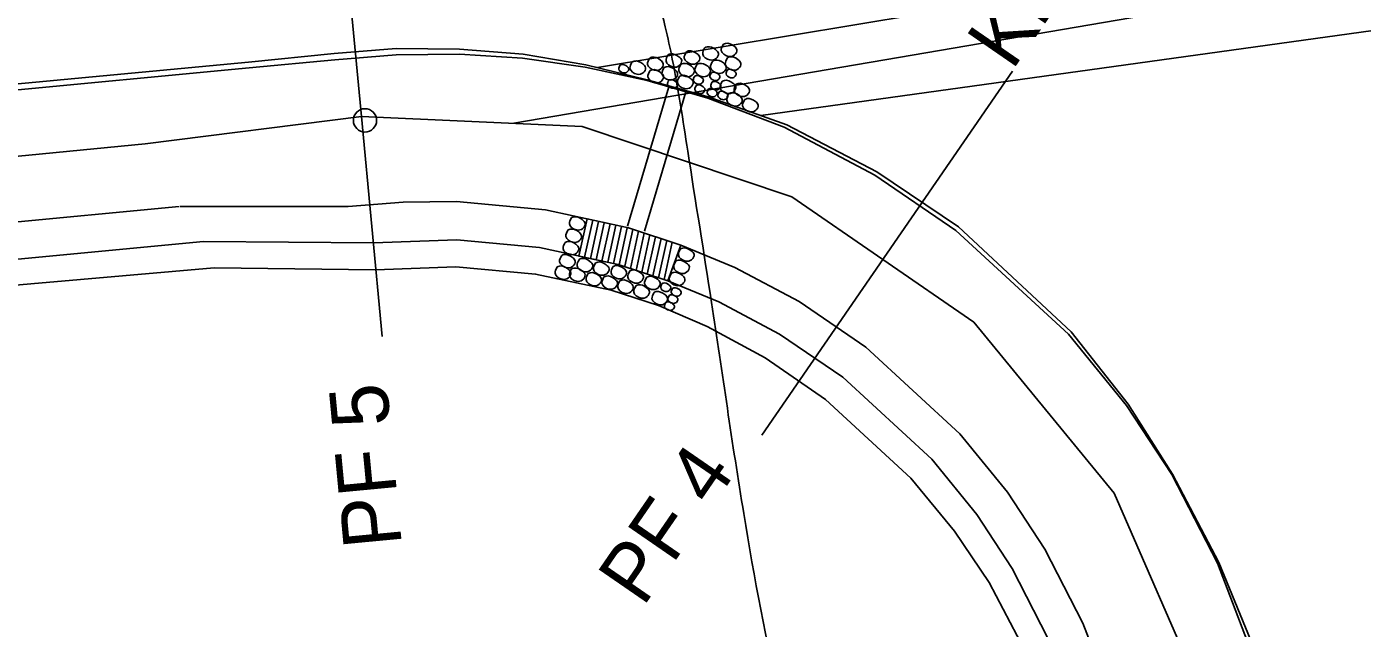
# Model space of a CAD drawing. Extents: x -478102 to -473059, y -1117705 to -1114104.
# Drawn here: x -476305.45 to -476260.09, y -1117061.5 to -1117041.09 of the extents above; entities that cross this region are included whole.
import ezdxf

# ---------------------------------------------------------------- set-up
doc = ezdxf.new("R2010")
doc.units = 0
for name, color, linetype in [('cesty', 7, 'Continuous'), ('el_vedeni__VN', 7, 'Continuous'), ('POLYGONY_SITUACE_PF', 7, 'Continuous'), ('POLYGONY_SITUACE_PF_POPISY', 7, 'Continuous'), ('POLYGONY_SITUACE_PO', 7, 'Continuous'), ('Vrstevnice_hlavni', 7, 'Continuous'), ('Vrstevnice_vedlejsi', 7, 'Continuous')]:
    doc.layers.add(name, color=color, linetype=linetype)

msp = doc.modelspace()

# ---------------------------------------------------------------- linework, layer by layer
for p, q in [((-476285.04, -1117047.856), (-476283.635, -1117043.126)), ((-476284.465, -1117048.027), (-476283.06, -1117043.297)), ((-476286.418, -1117047.609), (-476286.693, -1117048.868)), ((-476286.222, -1117047.651), (-476286.498, -1117048.911)), ((-476286.027, -1117047.694), (-476286.302, -1117048.954)), ((-476285.831, -1117047.737), (-476286.107, -1117048.996)), ((-476285.636, -1117047.78), (-476285.912, -1117049.039)), ((-476285.441, -1117047.822), (-476285.716, -1117049.082)), ((-476285.245, -1117047.865), (-476285.521, -1117049.125)), ((-476285.05, -1117047.908), (-476285.325, -1117049.167)), ((-476284.858, -1117047.965), (-476285.13, -1117049.21)), ((-476284.667, -1117048.027), (-476284.944, -1117049.294)), ((-476284.476, -1117048.09), (-476284.753, -1117049.356)), ((-476284.284, -1117048.152), (-476284.561, -1117049.419)), ((-476284.093, -1117048.214), (-476284.37, -1117049.481)), ((-476283.902, -1117048.276), (-476284.179, -1117049.543)), ((-476283.711, -1117048.338), (-476283.988, -1117049.605)), ((-476283.52, -1117048.401), (-476283.797, -1117049.667))]:
    msp.add_line(p, q)
msp.add_lwpolyline([(-476285.005, -1117047.917), (-476286.418, -1117047.609), (-476286.693, -1117048.868), (-476285.356, -1117049.16), (-476283.675, -1117049.707), (-476283.228, -1117048.496)], close=True)
for points in [[(-476283.041, -1117041.936), (-476283.114, -1117042.153), (-476282.875, -1117042.353), (-476282.664, -1117042.305), (-476282.583, -1117042.133), (-476282.679, -1117042.003), (-476282.969, -1117041.91), (-476283.041, -1117041.936)], [(-476282.414, -1117041.798), (-476282.487, -1117042.014), (-476282.247, -1117042.215), (-476282.036, -1117042.166), (-476281.955, -1117041.994), (-476282.052, -1117041.865), (-476282.341, -1117041.771), (-476282.414, -1117041.798)], [(-476281.786, -1117041.678), (-476281.859, -1117041.894), (-476281.62, -1117042.094), (-476281.409, -1117042.046), (-476281.327, -1117041.874), (-476281.424, -1117041.745), (-476281.713, -1117041.651), (-476281.786, -1117041.678)], [(-476285.292, -1117042.386), (-476285.338, -1117042.524), (-476285.185, -1117042.653), (-476285.05, -1117042.622), (-476284.998, -1117042.512), (-476285.06, -1117042.429), (-476285.245, -1117042.369), (-476285.292, -1117042.386)], [(-476284.885, -1117042.281), (-476284.958, -1117042.497), (-476284.719, -1117042.697), (-476284.508, -1117042.649), (-476284.427, -1117042.477), (-476284.523, -1117042.347), (-476284.812, -1117042.254), (-476284.885, -1117042.281)], [(-476284.287, -1117042.149), (-476284.36, -1117042.365), (-476284.121, -1117042.566), (-476283.91, -1117042.517), (-476283.829, -1117042.345), (-476283.925, -1117042.216), (-476284.215, -1117042.122), (-476284.287, -1117042.149)], [(-476283.66, -1117042.038), (-476283.733, -1117042.254), (-476283.494, -1117042.455), (-476283.283, -1117042.406), (-476283.201, -1117042.235), (-476283.298, -1117042.105), (-476283.587, -1117042.011), (-476283.66, -1117042.038)], [(-476283.228, -1117042.361), (-476283.301, -1117042.577), (-476283.062, -1117042.778), (-476282.851, -1117042.73), (-476282.769, -1117042.558), (-476282.866, -1117042.428), (-476283.155, -1117042.335), (-476283.228, -1117042.361)], [(-476282.681, -1117042.361), (-476282.754, -1117042.577), (-476282.515, -1117042.778), (-476282.304, -1117042.73), (-476282.223, -1117042.558), (-476282.319, -1117042.428), (-476282.609, -1117042.335), (-476282.681, -1117042.361)], [(-476282.146, -1117042.25), (-476282.219, -1117042.467), (-476281.98, -1117042.667), (-476281.769, -1117042.619), (-476281.687, -1117042.447), (-476281.784, -1117042.317), (-476282.073, -1117042.224), (-476282.146, -1117042.25)], [(-476281.647, -1117042.14), (-476281.72, -1117042.356), (-476281.481, -1117042.556), (-476281.27, -1117042.508), (-476281.189, -1117042.336), (-476281.285, -1117042.206), (-476281.575, -1117042.113), (-476281.647, -1117042.14)], [(-476284.278, -1117042.574), (-476284.351, -1117042.79), (-476284.112, -1117042.99), (-476283.901, -1117042.942), (-476283.82, -1117042.77), (-476283.916, -1117042.641), (-476284.205, -1117042.547), (-476284.278, -1117042.574)], [(-476283.798, -1117042.472), (-476283.871, -1117042.688), (-476283.632, -1117042.889), (-476283.421, -1117042.841), (-476283.34, -1117042.669), (-476283.436, -1117042.539), (-476283.725, -1117042.445), (-476283.798, -1117042.472)], [(-476283.272, -1117042.768), (-476283.345, -1117042.984), (-476283.106, -1117043.184), (-476282.895, -1117043.136), (-476282.813, -1117042.964), (-476282.91, -1117042.834), (-476283.199, -1117042.741), (-476283.272, -1117042.768)], [(-476282.76, -1117042.766), (-476282.807, -1117042.904), (-476282.653, -1117043.033), (-476282.518, -1117043.002), (-476282.466, -1117042.892), (-476282.528, -1117042.809), (-476282.713, -1117042.749), (-476282.76, -1117042.766)], [(-476282.195, -1117042.645), (-476282.242, -1117042.783), (-476282.089, -1117042.911), (-476281.954, -1117042.88), (-476281.902, -1117042.77), (-476281.964, -1117042.687), (-476282.149, -1117042.628), (-476282.195, -1117042.645)], [(-476281.647, -1117042.55), (-476281.694, -1117042.688), (-476281.541, -1117042.816), (-476281.406, -1117042.785), (-476281.353, -1117042.675), (-476281.415, -1117042.592), (-476281.6, -1117042.533), (-476281.647, -1117042.55)], [(-476283.641, -1117042.903), (-476283.687, -1117043.042), (-476283.534, -1117043.17), (-476283.399, -1117043.139), (-476283.347, -1117043.029), (-476283.409, -1117042.946), (-476283.594, -1117042.886), (-476283.641, -1117042.903)], [(-476282.707, -1117043.083), (-476282.754, -1117043.221), (-476282.601, -1117043.349), (-476282.466, -1117043.319), (-476282.414, -1117043.209), (-476282.475, -1117043.126), (-476282.661, -1117043.066), (-476282.707, -1117043.083)], [(-476282.29, -1117043.199), (-476282.337, -1117043.337), (-476282.184, -1117043.466), (-476282.049, -1117043.435), (-476281.997, -1117043.325), (-476282.059, -1117043.242), (-476282.244, -1117043.182), (-476282.29, -1117043.199)], [(-476282.169, -1117042.961), (-476282.216, -1117043.1), (-476282.063, -1117043.228), (-476281.928, -1117043.197), (-476281.876, -1117043.087), (-476281.937, -1117043.004), (-476282.123, -1117042.944), (-476282.169, -1117042.961)], [(-476281.926, -1117043.296), (-476281.972, -1117043.434), (-476281.819, -1117043.562), (-476281.684, -1117043.531), (-476281.632, -1117043.421), (-476281.694, -1117043.338), (-476281.879, -1117043.279), (-476281.926, -1117043.296)], [(-476281.823, -1117042.934), (-476281.896, -1117043.15), (-476281.657, -1117043.351), (-476281.446, -1117043.302), (-476281.364, -1117043.13), (-476281.461, -1117043.001), (-476281.75, -1117042.907), (-476281.823, -1117042.934)], [(-476281.352, -1117043.036), (-476281.425, -1117043.252), (-476281.186, -1117043.452), (-476280.975, -1117043.404), (-476280.894, -1117043.232), (-476280.99, -1117043.102), (-476281.279, -1117043.009), (-476281.352, -1117043.036)], [(-476281.601, -1117043.359), (-476281.674, -1117043.575), (-476281.435, -1117043.775), (-476281.224, -1117043.727), (-476281.143, -1117043.555), (-476281.239, -1117043.426), (-476281.529, -1117043.332), (-476281.601, -1117043.359)], [(-476281.061, -1117043.555), (-476281.134, -1117043.771), (-476280.895, -1117043.971), (-476280.684, -1117043.923), (-476280.602, -1117043.751), (-476280.699, -1117043.622), (-476280.988, -1117043.528), (-476281.061, -1117043.555)], [(-476286.94, -1117047.565), (-476287.013, -1117047.781), (-476286.774, -1117047.982), (-476286.563, -1117047.933), (-476286.482, -1117047.762), (-476286.578, -1117047.632), (-476286.867, -1117047.538), (-476286.94, -1117047.565)], [(-476287.061, -1117047.985), (-476287.134, -1117048.202), (-476286.895, -1117048.402), (-476286.684, -1117048.354), (-476286.603, -1117048.182), (-476286.699, -1117048.052), (-476286.988, -1117047.959), (-476287.061, -1117047.985)], [(-476287.155, -1117048.405), (-476287.228, -1117048.621), (-476286.988, -1117048.821), (-476286.777, -1117048.773), (-476286.696, -1117048.601), (-476286.793, -1117048.471), (-476287.082, -1117048.378), (-476287.155, -1117048.405)], [(-476283.241, -1117048.624), (-476283.314, -1117048.84), (-476283.075, -1117049.041), (-476282.864, -1117048.993), (-476282.782, -1117048.821), (-476282.879, -1117048.691), (-476283.168, -1117048.597), (-476283.241, -1117048.624)], [(-476287.276, -1117048.848), (-476287.349, -1117049.065), (-476287.11, -1117049.265), (-476286.899, -1117049.217), (-476286.817, -1117049.045), (-476286.914, -1117048.915), (-476287.203, -1117048.822), (-476287.276, -1117048.848)], [(-476286.681, -1117048.984), (-476286.754, -1117049.2), (-476286.514, -1117049.4), (-476286.304, -1117049.352), (-476286.222, -1117049.18), (-476286.319, -1117049.05), (-476286.608, -1117048.957), (-476286.681, -1117048.984)], [(-476286.126, -1117049.102), (-476286.199, -1117049.318), (-476285.96, -1117049.518), (-476285.749, -1117049.47), (-476285.668, -1117049.298), (-476285.764, -1117049.169), (-476286.053, -1117049.075), (-476286.126, -1117049.102)], [(-476285.53, -1117049.223), (-476285.603, -1117049.439), (-476285.364, -1117049.64), (-476285.153, -1117049.592), (-476285.072, -1117049.42), (-476285.168, -1117049.29), (-476285.457, -1117049.196), (-476285.53, -1117049.223)], [(-476283.399, -1117049.041), (-476283.472, -1117049.257), (-476283.233, -1117049.458), (-476283.022, -1117049.409), (-476282.941, -1117049.238), (-476283.037, -1117049.108), (-476283.326, -1117049.014), (-476283.399, -1117049.041)], [(-476287.429, -1117049.239), (-476287.502, -1117049.455), (-476287.263, -1117049.656), (-476287.052, -1117049.607), (-476286.97, -1117049.435), (-476287.067, -1117049.306), (-476287.356, -1117049.212), (-476287.429, -1117049.239)], [(-476286.944, -1117049.308), (-476287.017, -1117049.524), (-476286.777, -1117049.724), (-476286.566, -1117049.676), (-476286.485, -1117049.504), (-476286.582, -1117049.374), (-476286.871, -1117049.281), (-476286.944, -1117049.308)], [(-476286.379, -1117049.461), (-476286.452, -1117049.677), (-476286.213, -1117049.877), (-476286.002, -1117049.829), (-476285.921, -1117049.657), (-476286.017, -1117049.527), (-476286.307, -1117049.434), (-476286.379, -1117049.461)], [(-476285.841, -1117049.577), (-476285.914, -1117049.793), (-476285.675, -1117049.993), (-476285.464, -1117049.945), (-476285.383, -1117049.773), (-476285.479, -1117049.644), (-476285.769, -1117049.55), (-476285.841, -1117049.577)], [(-476284.96, -1117049.371), (-476285.033, -1117049.587), (-476284.794, -1117049.788), (-476284.583, -1117049.739), (-476284.502, -1117049.567), (-476284.598, -1117049.438), (-476284.888, -1117049.344), (-476284.96, -1117049.371)], [(-476284.391, -1117049.587), (-476284.464, -1117049.803), (-476284.225, -1117050.004), (-476284.014, -1117049.956), (-476283.932, -1117049.784), (-476284.029, -1117049.654), (-476284.318, -1117049.561), (-476284.391, -1117049.587)], [(-476283.552, -1117049.453), (-476283.625, -1117049.669), (-476283.386, -1117049.869), (-476283.175, -1117049.821), (-476283.094, -1117049.649), (-476283.19, -1117049.52), (-476283.479, -1117049.426), (-476283.552, -1117049.453)], [(-476285.303, -1117049.714), (-476285.376, -1117049.93), (-476285.137, -1117050.131), (-476284.926, -1117050.082), (-476284.845, -1117049.91), (-476284.941, -1117049.781), (-476285.231, -1117049.687), (-476285.303, -1117049.714)], [(-476284.755, -1117049.878), (-476284.828, -1117050.094), (-476284.589, -1117050.294), (-476284.378, -1117050.246), (-476284.296, -1117050.074), (-476284.393, -1117049.944), (-476284.682, -1117049.851), (-476284.755, -1117049.878)], [(-476284.138, -1117050.105), (-476284.211, -1117050.321), (-476283.971, -1117050.521), (-476283.76, -1117050.473), (-476283.679, -1117050.301), (-476283.775, -1117050.171), (-476284.065, -1117050.078), (-476284.138, -1117050.105)], [(-476283.869, -1117049.803), (-476283.915, -1117049.941), (-476283.762, -1117050.069), (-476283.627, -1117050.039), (-476283.575, -1117049.929), (-476283.637, -1117049.846), (-476283.822, -1117049.786), (-476283.869, -1117049.803)], [(-476283.511, -1117049.965), (-476283.558, -1117050.103), (-476283.405, -1117050.231), (-476283.27, -1117050.2), (-476283.218, -1117050.09), (-476283.28, -1117050.007), (-476283.465, -1117049.948), (-476283.511, -1117049.965)], [(-476283.74, -1117050.444), (-476283.787, -1117050.583), (-476283.634, -1117050.711), (-476283.499, -1117050.68), (-476283.447, -1117050.57), (-476283.509, -1117050.487), (-476283.694, -1117050.427), (-476283.74, -1117050.444)], [(-476283.624, -1117050.205), (-476283.671, -1117050.344), (-476283.518, -1117050.472), (-476283.383, -1117050.441), (-476283.33, -1117050.331), (-476283.392, -1117050.248), (-476283.577, -1117050.188), (-476283.624, -1117050.205)]]:
    msp.add_spline(points, degree=3)
at = {"layer": 'cesty'}
for p, q in [((-476295.004, -1117041.991), (-476292.905, -1117041.828)), ((-476292.905, -1117041.828), (-476290.743, -1117041.847)), ((-476290.743, -1117041.847), (-476288.59, -1117042.021)), ((-476307.101, -1117043.152), (-476297.916, -1117042.284)), ((-476297.916, -1117042.284), (-476295.004, -1117041.991)), ((-476297.897, -1117042.483), (-476294.983, -1117042.207)), ((-476294.983, -1117042.207), (-476292.895, -1117042.042)), ((-476292.895, -1117042.042), (-476290.747, -1117042.021)), ((-476290.747, -1117042.021), (-476288.604, -1117042.159)), ((-476288.604, -1117042.159), (-476286.477, -1117042.455)), ((-476288.59, -1117042.021), (-476286.463, -1117042.376)), ((-476306.565, -1117043.303), (-476297.897, -1117042.483)), ((-476286.477, -1117042.455), (-476284.378, -1117042.908)), ((-476286.463, -1117042.376), (-476284.374, -1117042.894)), ((-476284.378, -1117042.908), (-476282.318, -1117043.515)), ((-476284.374, -1117042.894), (-476282.3, -1117043.463)), ((-476282.318, -1117043.515), (-476279.727, -1117044.491)), ((-476282.3, -1117043.463), (-476279.635, -1117044.419)), ((-476279.727, -1117044.491), (-476276.645, -1117046.126)), ((-476279.635, -1117044.419), (-476276.577, -1117046.014)), ((-476276.645, -1117046.126), (-476273.889, -1117047.998)), ((-476276.577, -1117046.014), (-476273.801, -1117047.883)), ((-476370.99, -1117053.846), (-476300.265, -1117047.192)), ((-476300.236, -1117047.189), (-476294.527, -1117047.186)), ((-476300.236, -1117047.189), (-476300.236, -1117047.189)), ((-476294.527, -1117047.186), (-476292.663, -1117047.038)), ((-476292.663, -1117047.038), (-476290.846, -1117047.02)), ((-476290.846, -1117047.02), (-476287.83, -1117047.3)), ((-476287.83, -1117047.3), (-476285.005, -1117047.917)), ((-476285.005, -1117047.917), (-476283.228, -1117048.496)), ((-476273.889, -1117047.998), (-476270.059, -1117051.524)), ((-476273.801, -1117047.883), (-476269.975, -1117051.447)), ((-476299.448, -1117048.375), (-476370.868, -1117055.132)), ((-476299.448, -1117048.375), (-476299.448, -1117048.375)), ((-476293.674, -1117048.424), (-476299.448, -1117048.375)), ((-476290.844, -1117048.315), (-476293.674, -1117048.424)), ((-476288.03, -1117048.576), (-476290.844, -1117048.315)), ((-476285.356, -1117049.16), (-476288.03, -1117048.576)), ((-476283.228, -1117048.496), (-476281.395, -1117049.259)), ((-476283.675, -1117049.707), (-476285.356, -1117049.16)), ((-476281.395, -1117049.259), (-476279.216, -1117050.416)), ((-476281.942, -1117050.429), (-476283.675, -1117049.707)), ((-476279.879, -1117051.525), (-476281.942, -1117050.429)), ((-476279.216, -1117050.416), (-476276.946, -1117051.958)), ((-476277.732, -1117052.983), (-476279.879, -1117051.525)), ((-476270.059, -1117051.524), (-476268.093, -1117053.939)), ((-476269.975, -1117051.447), (-476268.033, -1117053.896)), ((-476276.946, -1117051.958), (-476273.752, -1117054.898)), ((-476274.708, -1117055.766), (-476277.732, -1117052.983)), ((-476268.093, -1117053.939), (-476266.552, -1117056.287)), ((-476268.033, -1117053.896), (-476266.535, -1117056.277)), ((-476273.752, -1117054.898), (-476272.135, -1117056.886)), ((-476273.179, -1117057.645), (-476274.708, -1117055.766)), ((-476266.552, -1117056.287), (-476265.008, -1117059.295)), ((-476266.535, -1117056.277), (-476264.959, -1117059.274)), ((-476272.135, -1117056.886), (-476270.863, -1117058.822)), ((-476271.976, -1117059.478), (-476273.179, -1117057.645)), ((-476269.578, -1117061.325), (-476270.863, -1117058.822)), ((-476270.762, -1117061.842), (-476271.976, -1117059.478)), ((-476268.718, -1117063.566), (-476269.578, -1117061.325))]:
    msp.add_line(p, q, dxfattribs=at)
for points in [[(-476299.076, -1117049.264), (-476370.83, -1117055.53)], [(-476266.732, -1117074.511), (-476270.768, -1117064.204), (-476271.566, -1117062.212), (-476272.761, -1117059.954), (-476273.936, -1117058.207), (-476275.415, -1117056.411), (-476278.317, -1117053.74), (-476280.366, -1117052.325), (-476282.34, -1117051.259), (-476283.992, -1117050.544), (-476285.595, -1117050.022), (-476288.167, -1117049.481), (-476290.873, -1117049.234), (-476293.603, -1117049.34), (-476293.603, -1117049.34), (-476299.076, -1117049.264)], [(-476265.008, -1117059.295), (-476263.985, -1117061.96), (-476262.821, -1117066.053)], [(-476264.959, -1117059.274), (-476263.868, -1117061.922), (-476262.685, -1117066.063)]]:
    msp.add_lwpolyline(points, dxfattribs=at)
at = {"layer": 'el_vedeni__VN'}
for points in [[(-476286.063, -1117042.475), (-476255.471, -1117037.386)], [(-476280.518, -1117044.102), (-476254.906, -1117040.545)]]:
    msp.add_lwpolyline(points, dxfattribs=at)
at = {"layer": 'POLYGONY_SITUACE_PF'}
for points in [[(-476293.374, -1117051.597), (-476294.08, -1117044.131), (-476294.787, -1117036.664)], [(-476280.478, -1117054.949), (-476276.224, -1117048.772), (-476271.971, -1117042.595)]]:
    msp.add_lwpolyline(points, dxfattribs=at)
at = {"layer": 'POLYGONY_SITUACE_PO'}
for points in [[(-476301.427, -1117045.065), (-476372.905, -1117052.019), (-476378.974, -1117051.908), (-476382.069, -1117051.436), (-476384.865, -1117050.444), (-476390.281, -1117047.7), (-476394.946, -1117043.817), (-476398.626, -1117038.989), (-476458.957, -1116938.029), (-476465.394, -1116926.586), (-476471.221, -1116914.82), (-476476.422, -1116902.765), (-476480.983, -1116890.454), (-476499.392, -1116836.452), (-476499.929, -1116834.228), (-476500.052, -1116831.944), (-476499.756, -1116829.676), (-476499.052, -1116827.5), (-476496.647, -1116821.88)], [(-476215.821, -1117031.882), (-476288.898, -1117044.364)], [(-476250.954, -1117100.054), (-476256.772, -1117095.342), (-476265.518, -1117063.797), (-476268.51, -1117056.912), (-476273.282, -1117051.116), (-476279.465, -1117046.859), (-476286.581, -1117044.469), (-476294.08, -1117044.131), (-476301.427, -1117045.065)]]:
    msp.add_lwpolyline(points, dxfattribs=at)
msp.add_circle((-476293.959, -1117044.265), 0.395, dxfattribs=at)
at = {"layer": 'Vrstevnice_hlavni'}
msp.add_spline([(-476249.493, -1117108.392), (-476249.775, -1117107.699), (-476250.264, -1117106.97), (-476250.958, -1117106.207), (-476251.857, -1117105.408), (-476252.513, -1117105.14), (-476252.925, -1117105.402), (-476253.095, -1117106.195), (-476253.235, -1117107.1), (-476253.347, -1117108.118), (-476253.43, -1117109.248), (-476253.596, -1117109.985), (-476253.847, -1117110.328), (-476254.181, -1117110.278), (-476255.528, -1117110.336), (-476257.887, -1117110.502), (-476261.259, -1117110.776), (-476263.654, -1117110.928), (-476265.074, -1117110.957), (-476265.519, -1117110.863), (-476266.5, -1117108.002), (-476268.017, -1117102.375), (-476270.071, -1117093.98), (-476271.569, -1117088.098), (-476272.511, -1117084.73), (-476272.897, -1117083.874), (-476273.181, -1117083.184), (-476273.365, -1117082.66), (-476273.447, -1117082.301), (-476273.665, -1117081.937), (-476274.021, -1117081.569), (-476274.513, -1117081.196), (-476274.898, -1117080.887), (-476275.174, -1117080.644), (-476275.342, -1117080.466), (-476275.953, -1117078.624), (-476277.006, -1117075.118), (-476278.503, -1117069.948), (-476279.866, -1117064.113), (-476281.094, -1117057.612), (-476282.188, -1117050.447), (-476282.997, -1117045.306), (-476283.52, -1117042.188), (-476283.758, -1117041.094), (-476283.99, -1117040.218), (-476284.216, -1117039.561), (-476284.654, -1117038.684)], degree=3, dxfattribs=at)
at = {"layer": 'Vrstevnice_vedlejsi'}
msp.add_spline([(-476361.641, -1116910.017), (-476360.991, -1116911.137), (-476360.552, -1116912.67), (-476360.323, -1116914.616), (-476360.306, -1116916.973), (-476360.308, -1116918.585), (-476360.329, -1116919.449), (-476360.369, -1116919.567), (-476360.386, -1116919.663), (-476360.38, -1116919.738), (-476360.35, -1116919.79), (-476360.486, -1116921.699), (-476360.787, -1116925.464), (-476361.254, -1116931.086), (-476361.67, -1116935.051), (-476362.037, -1116937.36), (-476362.353, -1116938.012), (-476362.549, -1116938.736), (-476362.623, -1116939.532), (-476362.576, -1116940.398), (-476362.264, -1116942.869), (-476361.686, -1116946.945), (-476360.843, -1116952.626), (-476360.093, -1116958.73), (-476359.435, -1116965.256), (-476358.871, -1116972.204), (-476358.36, -1116977.092), (-476357.904, -1116979.919), (-476357.501, -1116980.685), (-476356.57, -1116984.99), (-476355.11, -1116992.835), (-476353.122, -1117004.219), (-476351.571, -1117012.905), (-476350.455, -1117018.893), (-476349.776, -1117022.183), (-476349.504, -1117027.698), (-476349.639, -1117035.437), (-476350.182, -1117045.4), (-476350.307, -1117053.191), (-476350.012, -1117058.811), (-476349.298, -1117062.259), (-476350.091, -1117065.67), (-476352.39, -1117069.042), (-476356.195, -1117072.377), (-476359.92, -1117076.705), (-476363.566, -1117082.026), (-476367.131, -1117088.339), (-476371.33, -1117094.641), (-476376.164, -1117100.933), (-476381.631, -1117107.213), (-476386.474, -1117112.181), (-476390.692, -1117115.834), (-476394.286, -1117118.174), (-476397.491, -1117120.393), (-476400.306, -1117122.492), (-476402.732, -1117124.472), (-476402.928, -1117127.738), (-476400.894, -1117132.291), (-476396.631, -1117138.131), (-476389.647, -1117141.585), (-476379.944, -1117142.653), (-476367.521, -1117141.334), (-476355.525, -1117141.406), (-476343.957, -1117142.868), (-476332.816, -1117145.722), (-476324.482, -1117147.814), (-476318.952, -1117149.144), (-476316.229, -1117149.714), (-476310.745, -1117150.91), (-476302.502, -1117152.733), (-476291.498, -1117155.183), (-476284.107, -1117156.821), (-476280.33, -1117157.647), (-476280.165, -1117157.662), (-476279.816, -1117157.743), (-476279.284, -1117157.891), (-476278.569, -1117158.106), (-476278.072, -1117158.306), (-476277.796, -1117158.489), (-476277.739, -1117158.657), (-476277.684, -1117158.815), (-476277.629, -1117158.963), (-476277.576, -1117159.102), (-476277.523, -1117159.234), (-476277.472, -1117159.361), (-476277.423, -1117159.482), (-476277.379, -1117159.591), (-476277.34, -1117159.689), (-476277.307, -1117159.775), (-476277.275, -1117159.863), (-476277.243, -1117159.954), (-476277.212, -1117160.046), (-476277.173, -1117160.139), (-476277.129, -1117160.233), (-476277.078, -1117160.326), (-476277.04, -1117160.421), (-476277.015, -1117160.516)], degree=3, dxfattribs=at)

# ---------------------------------------------------------------- texts
at = {"layer": 'POLYGONY_SITUACE_PF_POPISY'}
for s, rotation, p in [('KM=0.056', 55.4518, (-476271.978, -1117042.605)), ('PF 5', 95.4072, (-476292.703, -1117058.681)), ('PF 4', 55.4518, (-476284.513, -1117060.81))]:
    msp.add_text(s, height=1.9765, rotation=rotation, dxfattribs=at).set_placement(p)

doc.saveas('drawing.dxf')
